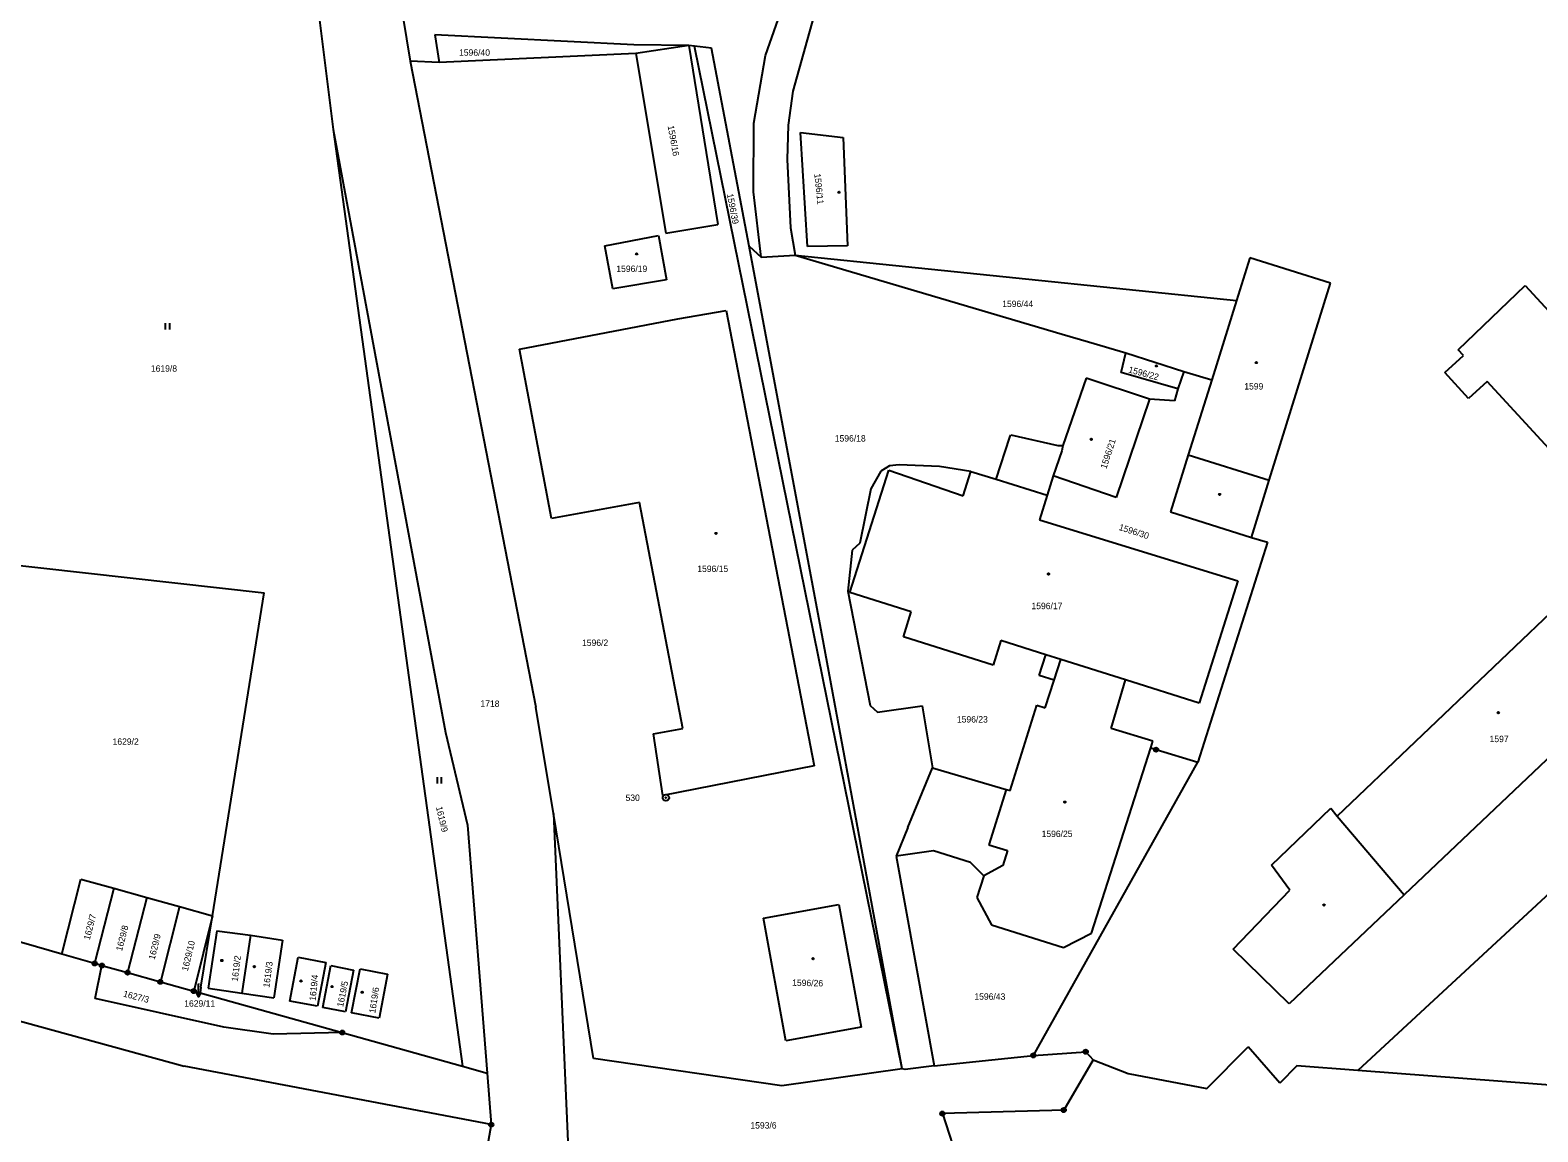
# Model space of a CAD drawing. Extents: x -762761 to -760936, y -1154749 to -1152377.
# Drawn here: x -762540.2 to -762363.4, y -1152937 to -1152807.9 of the extents above; entities that cross this region are included whole.
import ezdxf

# ---------------------------------------------------------------- set-up
doc = ezdxf.new("R2010")
doc.units = 0
for name, color, linetype in [('NTL_VÝŠKA', 7, 'Continuous'), ('NTL_ZNAČKA', 7, 'Continuous'), ('NTL_ČÍSLO', 7, 'Continuous'), ('PKO_VÝŠKA', 7, 'Continuous'), ('PKO_ZNAČKA', 7, 'Continuous'), ('PKO_ČÍSLO', 7, 'Continuous'), ('PZS_POL_ČÍSLO', 7, 'Continuous'), ('ZP_KÓTY', 7, 'Continuous')]:
    doc.layers.add(name, color=color, linetype=linetype)

msp = doc.modelspace()

# ---------------------------------------------------------------- linework, layer by layer
at = {"layer": 'NTL_VÝŠKA'}
for p, q in [((-762404.38, -1152857.65), (-762394.89, -1152860.6)), ((-762426.91, -1152860.5), (-762420.91, -1152862.37)), ((-762420.09, -1152884.04), (-762419.31, -1152881.63)), ((-762425.73, -1152896.86), (-762427.76, -1152903.35)), ((-762386.93, -1152899.98), (-762379.05, -1152909.21)), ((-762427.76, -1152903.35), (-762425.58, -1152904.03)), ((-762425.58, -1152904.03), (-762426.13, -1152905.79)), ((-762426.13, -1152905.79), (-762428.36, -1152906.98))]:
    msp.add_line(p, q, dxfattribs=at)
at = {"layer": 'NTL_ZNAČKA'}
for p, q in [((-762508.36, -1152789.42), (-762504.64, -1152819.5)), ((-762499.2, -1152789.04), (-762495.62, -1152811.48)), ((-762453.95, -1152810.83), (-762451.93, -1152805.15)), ((-762448.3, -1152806.34), (-762450.74, -1152815.01)), ((-762492.69, -1152808.38), (-762492.22, -1152811.65)), ((-762469.39, -1152809.59), (-762492.69, -1152808.38)), ((-762462.93, -1152809.65), (-762469.39, -1152809.59)), ((-762462.93, -1152809.65), (-762469.13, -1152810.58)), ((-762462.27, -1152809.73), (-762462.93, -1152809.65)), ((-762462.93, -1152809.65), (-762459.52, -1152830.62)), ((-762437.93, -1152929.63), (-762462.27, -1152809.73)), ((-762460.27, -1152809.97), (-762462.27, -1152809.73)), ((-762455.84, -1152833.17), (-762460.27, -1152809.97)), ((-762492.22, -1152811.65), (-762495.62, -1152811.48)), ((-762495.62, -1152811.48), (-762480.87, -1152887.2)), ((-762469.13, -1152810.58), (-762492.22, -1152811.65)), ((-762469.13, -1152810.58), (-762465.63, -1152831.66)), ((-762455.3, -1152818.77), (-762453.95, -1152810.83)), ((-762450.74, -1152815.01), (-762451.29, -1152818.99)), ((-762455.35, -1152826.79), (-762455.3, -1152818.77)), ((-762504.64, -1152819.5), (-762491.44, -1152890.19)), ((-762504.64, -1152819.5), (-762489.47, -1152929.3)), ((-762451.29, -1152818.99), (-762451.4, -1152823.03)), ((-762449, -1152833.23), (-762449.83, -1152819.85)), ((-762449.83, -1152819.85), (-762444.82, -1152820.43)), ((-762444.82, -1152820.43), (-762444.33, -1152833.14)), ((-762451.4, -1152823.03), (-762451.02, -1152831.04)), ((-762454.43, -1152834.46), (-762455.35, -1152826.79)), ((-762465.63, -1152831.66), (-762459.52, -1152830.62)), ((-762451.02, -1152831.04), (-762450.47, -1152834.22)), ((-762472.79, -1152833.12), (-762466.5, -1152831.93)), ((-762466.5, -1152831.93), (-762465.53, -1152837.11)), ((-762471.84, -1152838.18), (-762472.79, -1152833.12)), ((-762447.09, -1152879.89), (-762455.84, -1152833.17)), ((-762455.84, -1152833.17), (-762454.43, -1152834.46)), ((-762454.43, -1152834.46), (-762450.47, -1152834.22)), ((-762450.47, -1152834.22), (-762398.71, -1152839.55)), ((-762450.47, -1152834.22), (-762419.16, -1152843.48)), ((-762444.33, -1152833.14), (-762449, -1152833.23)), ((-762397.15, -1152834.56), (-762398.71, -1152839.55)), ((-762387.69, -1152837.5), (-762397.15, -1152834.56)), ((-762465.53, -1152837.11), (-762471.84, -1152838.18)), ((-762394.89, -1152860.6), (-762387.69, -1152837.5)), ((-762372.75, -1152845.31), (-762364.88, -1152837.77)), ((-762364.88, -1152837.77), (-762343.11, -1152861.47)), ((-762398.71, -1152839.55), (-762401.61, -1152848.86)), ((-762482.78, -1152845.26), (-762464.23, -1152841.68)), ((-762464.23, -1152841.68), (-762458.55, -1152840.73)), ((-762458.55, -1152840.73), (-762448.22, -1152894.08)), ((-762419.16, -1152843.48), (-762416.09, -1152844.39)), ((-762479.04, -1152865.11), (-762482.78, -1152845.26)), ((-762416.09, -1152844.39), (-762411.68, -1152845.69)), ((-762372.12, -1152846), (-762372.75, -1152845.31)), ((-762412.26, -1152848), (-762411.68, -1152845.69)), ((-762411.68, -1152845.69), (-762404.9, -1152847.85)), ((-762374.3, -1152848), (-762372.12, -1152846)), ((-762416.36, -1152848.63), (-762419.08, -1152856.55)), ((-762408.94, -1152851.12), (-762416.36, -1152848.63)), ((-762405.59, -1152849.89), (-762412.26, -1152848)), ((-762404.9, -1152847.85), (-762405.59, -1152849.89)), ((-762404.9, -1152847.85), (-762401.61, -1152848.86)), ((-762401.61, -1152848.86), (-762404.38, -1152857.65)), ((-762371.51, -1152851.04), (-762374.3, -1152848)), ((-762405.59, -1152849.89), (-762405.97, -1152851.31)), ((-762369.33, -1152849.04), (-762371.51, -1152851.04)), ((-762351.11, -1152868.88), (-762369.33, -1152849.04)), ((-762408.94, -1152851.12), (-762412.84, -1152862.62)), ((-762405.97, -1152851.31), (-762408.94, -1152851.12)), ((-762426.91, -1152860.5), (-762425.28, -1152855.58)), ((-762425.28, -1152855.58), (-762425.19, -1152855.3)), ((-762425.19, -1152855.3), (-762419.65, -1152856.56)), ((-762419.2, -1152857.15), (-762420.2, -1152860.1)), ((-762419.65, -1152856.56), (-762419.08, -1152856.55)), ((-762419.08, -1152856.55), (-762419.2, -1152857.15)), ((-762404.38, -1152857.65), (-762406.47, -1152864.31)), ((-762444.05, -1152873.78), (-762439.49, -1152859.42)), ((-762440.42, -1152859.54), (-762441.59, -1152861.61)), ((-762439.42, -1152858.91), (-762440.42, -1152859.54)), ((-762439.49, -1152859.42), (-762430.77, -1152862.43)), ((-762438.26, -1152858.79), (-762439.42, -1152858.91)), ((-762433.56, -1152859.01), (-762438.26, -1152858.79)), ((-762429.87, -1152859.58), (-762433.56, -1152859.01)), ((-762430.77, -1152862.43), (-762429.87, -1152859.58)), ((-762429.87, -1152859.58), (-762426.91, -1152860.5)), ((-762420.2, -1152860.1), (-762420.91, -1152862.37)), ((-762412.84, -1152862.62), (-762420.2, -1152860.1)), ((-762396.98, -1152867.31), (-762394.89, -1152860.6)), ((-762441.59, -1152861.61), (-762442.9, -1152867.99)), ((-762420.91, -1152862.37), (-762421.8, -1152865.25)), ((-762468.72, -1152863.23), (-762479.04, -1152865.11)), ((-762463.62, -1152889.73), (-762468.72, -1152863.23)), ((-762406.47, -1152864.31), (-762396.98, -1152867.31)), ((-762421.8, -1152865.25), (-762398.56, -1152872.39)), ((-762442.9, -1152867.99), (-762443.78, -1152868.82)), ((-762395.1, -1152867.87), (-762403.26, -1152893.68)), ((-762396.98, -1152867.31), (-762395.1, -1152867.87)), ((-762549.69, -1152869.67), (-762512.7, -1152873.81)), ((-762443.78, -1152868.82), (-762444.29, -1152873.63)), ((-762386.93, -1152899.98), (-762354.01, -1152868.62)), ((-762444.29, -1152873.63), (-762441.68, -1152887.02)), ((-762398.56, -1152872.39), (-762403.1, -1152886.76)), ((-762518.78, -1152911.67), (-762512.7, -1152873.81)), ((-762436.86, -1152876.06), (-762444.05, -1152873.78)), ((-762437.78, -1152878.96), (-762436.86, -1152876.06)), ((-762427.26, -1152882.29), (-762437.78, -1152878.96)), ((-762329.04, -1152878.48), (-762384.48, -1152929.81)), ((-762345.73, -1152877.59), (-762379.05, -1152909.21)), ((-762442, -1152907.52), (-762447.09, -1152879.89)), ((-762426.35, -1152879.41), (-762427.26, -1152882.29)), ((-762421.08, -1152881.08), (-762426.35, -1152879.41)), ((-762421.84, -1152883.49), (-762421.08, -1152881.08)), ((-762419.31, -1152881.63), (-762421.08, -1152881.08)), ((-762411.72, -1152884.03), (-762419.31, -1152881.63)), ((-762420.09, -1152884.04), (-762421.84, -1152883.49)), ((-762421.14, -1152887.3), (-762420.09, -1152884.04)), ((-762413.41, -1152889.73), (-762411.72, -1152884.03)), ((-762403.1, -1152886.76), (-762411.72, -1152884.03)), ((-762478.8, -1152899.7), (-762480.87, -1152887.2)), ((-762441.68, -1152887.02), (-762440.8, -1152887.81)), ((-762440.8, -1152887.81), (-762435.58, -1152887.05)), ((-762435.58, -1152887.05), (-762434.35, -1152894.32)), ((-762425.26, -1152896.97), (-762422.14, -1152886.97)), ((-762422.14, -1152886.97), (-762421.14, -1152887.3)), ((-762491.44, -1152890.19), (-762488.88, -1152901.06)), ((-762467.06, -1152890.33), (-762463.62, -1152889.73)), ((-762465.97, -1152897.57), (-762467.06, -1152890.33)), ((-762408.53, -1152891.2), (-762413.41, -1152889.73)), ((-762408.78, -1152892), (-762408.53, -1152891.2)), ((-762415.72, -1152913.73), (-762408.78, -1152892)), ((-762408.78, -1152892), (-762408.14, -1152892.2)), ((-762408.14, -1152892.2), (-762403.26, -1152893.68)), ((-762448.22, -1152894.08), (-762465.97, -1152897.57)), ((-762437.24, -1152901.34), (-762434.35, -1152894.32)), ((-762434.35, -1152894.32), (-762425.73, -1152896.86)), ((-762422.54, -1152928.05), (-762403.26, -1152893.68)), ((-762425.73, -1152896.86), (-762425.26, -1152896.97)), ((-762478.8, -1152899.7), (-762477.12, -1152938.13)), ((-762474.12, -1152928.41), (-762478.8, -1152899.7)), ((-762394.62, -1152905.75), (-762387.67, -1152899.06)), ((-762387.67, -1152899.06), (-762386.93, -1152899.98)), ((-762488.88, -1152901.06), (-762486.58, -1152930.11)), ((-762437.24, -1152901.34), (-762438.61, -1152904.67)), ((-762536.44, -1152916.16), (-762577.03, -1152904.55)), ((-762434.26, -1152904.08), (-762438.61, -1152904.67)), ((-762438.61, -1152904.67), (-762434.18, -1152929.26)), ((-762429.91, -1152905.41), (-762434.26, -1152904.08)), ((-762428.36, -1152906.98), (-762429.91, -1152905.41)), ((-762428.36, -1152906.98), (-762429.17, -1152909.52)), ((-762392.48, -1152908.67), (-762394.62, -1152905.75)), ((-762536.44, -1152916.16), (-762534.2, -1152907.38)), ((-762534.2, -1152907.38), (-762530.35, -1152908.45)), ((-762530.35, -1152908.45), (-762532.6, -1152917.27)), ((-762530.35, -1152908.45), (-762526.49, -1152909.52)), ((-762437.93, -1152929.63), (-762442, -1152907.52)), ((-762399.13, -1152915.6), (-762392.48, -1152908.67)), ((-762526.49, -1152909.52), (-762528.74, -1152918.34)), ((-762526.49, -1152909.52), (-762522.64, -1152910.6)), ((-762522.64, -1152910.6), (-762524.89, -1152919.42)), ((-762522.64, -1152910.6), (-762518.78, -1152911.67)), ((-762454.17, -1152911.95), (-762445.33, -1152910.35)), ((-762445.33, -1152910.35), (-762442.73, -1152924.75)), ((-762429.17, -1152909.52), (-762427.43, -1152912.74)), ((-762379.05, -1152909.21), (-762392.53, -1152922.01)), ((-762518.78, -1152911.67), (-762520.98, -1152920.5)), ((-762520.13, -1152920.06), (-762518.78, -1152911.67)), ((-762451.56, -1152926.34), (-762454.17, -1152911.95)), ((-762518.26, -1152913.43), (-762519.27, -1152920.16)), ((-762518.26, -1152913.43), (-762514.34, -1152913.96)), ((-762514.34, -1152913.96), (-762515.35, -1152920.75)), ((-762514.34, -1152913.96), (-762510.56, -1152914.52)), ((-762427.43, -1152912.74), (-762418.99, -1152915.38)), ((-762418.99, -1152915.38), (-762415.72, -1152913.73)), ((-762510.56, -1152914.52), (-762511.58, -1152921.31)), ((-762392.53, -1152922.01), (-762399.13, -1152915.6)), ((-762532.6, -1152917.27), (-762536.44, -1152916.16)), ((-762531.74, -1152917.51), (-762532.6, -1152917.27)), ((-762532.54, -1152921.39), (-762531.74, -1152917.51)), ((-762531.74, -1152917.51), (-762528.74, -1152918.34)), ((-762509.71, -1152921.67), (-762508.73, -1152916.52)), ((-762508.73, -1152916.52), (-762505.49, -1152917.15)), ((-762505.49, -1152917.15), (-762506.47, -1152922.29)), ((-762505.83, -1152922.41), (-762504.9, -1152917.52)), ((-762504.9, -1152917.52), (-762502.25, -1152918.04)), ((-762557.73, -1152919.56), (-762522.11, -1152929.29)), ((-762528.74, -1152918.34), (-762524.89, -1152919.42)), ((-762524.89, -1152919.42), (-762520.98, -1152920.5)), ((-762502.25, -1152918.04), (-762503.18, -1152922.92)), ((-762502.47, -1152923.06), (-762501.48, -1152917.91)), ((-762501.48, -1152917.91), (-762498.24, -1152918.53)), ((-762498.24, -1152918.53), (-762499.23, -1152923.68)), ((-762517.46, -1152924.74), (-762532.54, -1152921.39)), ((-762520.98, -1152920.5), (-762520.24, -1152920.71)), ((-762520.13, -1152920.06), (-762520.24, -1152920.71)), ((-762520.24, -1152920.71), (-762503.56, -1152925.36)), ((-762519.27, -1152920.16), (-762515.35, -1152920.75)), ((-762515.35, -1152920.75), (-762511.58, -1152921.31)), ((-762506.47, -1152922.29), (-762509.71, -1152921.67)), ((-762503.18, -1152922.92), (-762505.83, -1152922.41)), ((-762499.23, -1152923.68), (-762502.47, -1152923.06)), ((-762511.67, -1152925.56), (-762517.46, -1152924.74)), ((-762442.73, -1152924.75), (-762451.56, -1152926.34)), ((-762503.56, -1152925.36), (-762511.67, -1152925.56)), ((-762503.56, -1152925.36), (-762489.47, -1152929.3)), ((-762452.03, -1152931.61), (-762474.12, -1152928.41)), ((-762434.18, -1152929.26), (-762422.54, -1152928.05)), ((-762422.54, -1152928.05), (-762416.4, -1152927.61)), ((-762416.4, -1152927.61), (-762415.51, -1152928.57)), ((-762402.19, -1152931.91), (-762397.34, -1152927.04)), ((-762393.63, -1152931.29), (-762397.34, -1152927.04)), ((-762486.1, -1152936.16), (-762522.11, -1152929.29)), ((-762489.47, -1152929.3), (-762486.58, -1152930.11)), ((-762486.58, -1152930.11), (-762486.1, -1152936.16)), ((-762437.93, -1152929.63), (-762452.03, -1152931.61)), ((-762437.56, -1152929.7), (-762437.93, -1152929.63)), ((-762434.18, -1152929.26), (-762437.56, -1152929.7)), ((-762415.51, -1152928.57), (-762418.97, -1152934.45)), ((-762415.51, -1152928.57), (-762411.44, -1152930.18)), ((-762411.44, -1152930.18), (-762402.19, -1152931.91)), ((-762391.64, -1152929.26), (-762393.63, -1152931.29)), ((-762384.48, -1152929.81), (-762391.64, -1152929.26)), ((-762353.03, -1152932.21), (-762384.48, -1152929.81)), ((-762418.97, -1152934.45), (-762433.2, -1152934.87)), ((-762433.2, -1152934.87), (-762430.99, -1152941.66)), ((-762486.1, -1152936.16), (-762492.13, -1152970.38))]:
    msp.add_line(p, q, dxfattribs=at)
at = {"layer": 'NTL_ČÍSLO'}
for p, q in [((-762524.28, -1152842.94), (-762524.28, -1152842.19)), ((-762523.78, -1152842.94), (-762523.78, -1152842.19)), ((-762492.41, -1152896.16), (-762492.41, -1152895.41)), ((-762491.91, -1152896.16), (-762491.91, -1152895.41))]:
    msp.add_line(p, q, dxfattribs=at)
for centre in [(-762445.32, -1152826.85), (-762469.04, -1152834.08), (-762408.11, -1152847.21), (-762396.39, -1152846.82), (-762415.75, -1152855.82), (-762400.7, -1152862.28), (-762459.74, -1152866.85), (-762420.76, -1152871.61), (-762368.03, -1152887.86), (-762418.85, -1152898.35), (-762388.46, -1152910.42), (-762517.68, -1152916.92), (-762513.88, -1152917.65), (-762448.36, -1152916.7), (-762508.4, -1152919.32), (-762504.75, -1152919.97), (-762501.23, -1152920.64)]:
    msp.add_circle(centre, 0.0875, dxfattribs=at)
at = {"layer": 'PKO_ZNAČKA'}
for p in [(-762520.4, -1152919.63), (-762520.4, -1152921.19)]:
    msp.add_line(p, (-762520.4, -1152919.69), dxfattribs=at)
msp.add_lwpolyline([(-762520.15, -1152920.69), (-762520.4, -1152921.19), (-762520.65, -1152920.69)], dxfattribs=at)
at = {"layer": 'PKO_ČÍSLO'}
for centre, radius in [((-762408.14, -1152892.2), 0.25), ((-762408.14, -1152892.2), 0.05), ((-762465.62, -1152897.83), 0.375), ((-762465.62, -1152897.83), 0.05), ((-762532.6, -1152917.27), 0.25), ((-762532.6, -1152917.27), 0.05), ((-762531.74, -1152917.51), 0.25), ((-762531.74, -1152917.51), 0.05), ((-762528.74, -1152918.34), 0.25), ((-762528.74, -1152918.34), 0.05), ((-762524.89, -1152919.42), 0.25), ((-762524.89, -1152919.42), 0.05), ((-762520.98, -1152920.5), 0.25), ((-762520.98, -1152920.5), 0.05), ((-762503.56, -1152925.36), 0.25), ((-762503.56, -1152925.36), 0.05), ((-762422.54, -1152928.05), 0.25), ((-762422.54, -1152928.05), 0.05), ((-762416.4, -1152927.61), 0.25), ((-762416.4, -1152927.61), 0.05), ((-762433.2, -1152934.87), 0.25), ((-762433.2, -1152934.87), 0.05), ((-762418.97, -1152934.45), 0.25), ((-762418.97, -1152934.45), 0.05), ((-762486.1, -1152936.16), 0.25), ((-762486.1, -1152936.16), 0.05)]:
    msp.add_circle(centre, radius, dxfattribs=at)

# ---------------------------------------------------------------- texts
at = {"layer": 'PKO_VÝŠKA'}
for s, p in [('1596/40', (-762489.87, -1152810.85)), ('1596/44', (-762426.19, -1152840.31)), ('1619/8', (-762526, -1152847.89)), ('1596/18', (-762445.82, -1152856.08)), ('1596/2', (-762475.45, -1152880.04)), ('1596/23', (-762431.5, -1152889.02)), ('1629/2', (-762530.49, -1152891.63)), ('1596/43', (-762429.45, -1152921.52)), ('1629/11', (-762522.09, -1152922.33)), ('1593/6', (-762455.71, -1152936.62))]:
    msp.add_text(s, height=0.75, dxfattribs=at).set_placement(p)
for s, rotation, p in [('1596/16', 280.291, (-762465.42, -1152819.09)), ('1596/39', 280.8639, (-762458.48, -1152827.08)), ('1596/30', 342.285, (-762412.58, -1152866.43)), ('1718', 358.7862, (-762487.37, -1152887.15)), ('1619/9', 283.0984, (-762492.58, -1152898.94)), ('1629/7', 75.8023, (-762533.17, -1152914.57)), ('1629/8', 75.4585, (-762529.39, -1152915.87)), ('1629/9', 76.1461, (-762525.56, -1152916.88)), ('1629/10', 76.4326, (-762521.67, -1152918.22)), ('1627/3', 345.6654, (-762529.3, -1152921.14))]:
    msp.add_text(s, height=0.75, rotation=rotation, dxfattribs=at).set_placement(p)
at = {"layer": 'PZS_POL_ČÍSLO'}
msp.add_text('530', height=0.75, dxfattribs=at).set_placement((-762470.35, -1152898.21))
at = {"layer": 'ZP_KÓTY'}
for s, rotation, p in [('1596/11', 276.1657, (-762448.23, -1152824.7)), ('1596/22', 344.9779, (-762411.45, -1152847.97)), ('1596/21', 71.9062, (-762413.98, -1152859.35)), ('1619/2', 83.1935, (-762515.81, -1152919.42)), ('1619/3', 82.4486, (-762512.11, -1152920.13)), ('1619/4', 84.2248, (-762506.69, -1152921.67)), ('1619/5', 78.4379, (-762503.47, -1152922.42)), ('1596/26', 358.7289, (-762450.82, -1152919.88)), ('1619/6', 81.3027, (-762499.69, -1152923.14))]:
    msp.add_text(s, height=0.75, rotation=rotation, dxfattribs=at).set_placement(p)
for s, p in [('1596/19', (-762471.43, -1152836.2)), ('1599', (-762397.81, -1152849.98)), ('1596/15', (-762461.94, -1152871.37)), ('1596/17', (-762422.76, -1152875.73)), ('1597', (-762369.05, -1152891.32)), ('1596/25', (-762421.57, -1152902.44))]:
    msp.add_text(s, height=0.75, dxfattribs=at).set_placement(p)

doc.saveas('drawing.dxf')
